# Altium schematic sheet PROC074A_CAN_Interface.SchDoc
size 431 x 279 mm; Date: Not shown in title block; ApprovedBy: Not shown in title block; CheckedBy: Not shown in title block; Author: Not shown in title block; CompanyName: Not shown in title block; Engineer: Not shown in title block; Organization: Not shown in title block; Address1: Not shown in title block; Address2: Not shown in title block; Address3: Not shown in title block; Address4: Not shown in title block; DocumentNumber: 1; Revision: Use project parameter SCH_Rev; SheetNumber: 13; SheetTotal: 22; PageSetup: Record=PageOptions¦CenterHorizontal=True¦CenterVertical=True¦PrintScale=1.00¦XCorrection=1.00¦YCorrection=1.00¦PrintKind=0¦BorderSize=5000000¦LeftOffset=0¦BottomOffset=0¦Orientation=2¦PaperLength=1000¦PaperWidth=1000¦Scale=100¦PaperSource=15¦PrintQuality=600¦MediaType=1¦DitherType=10¦PaperKind=Letter¦PrintScaleMode=1
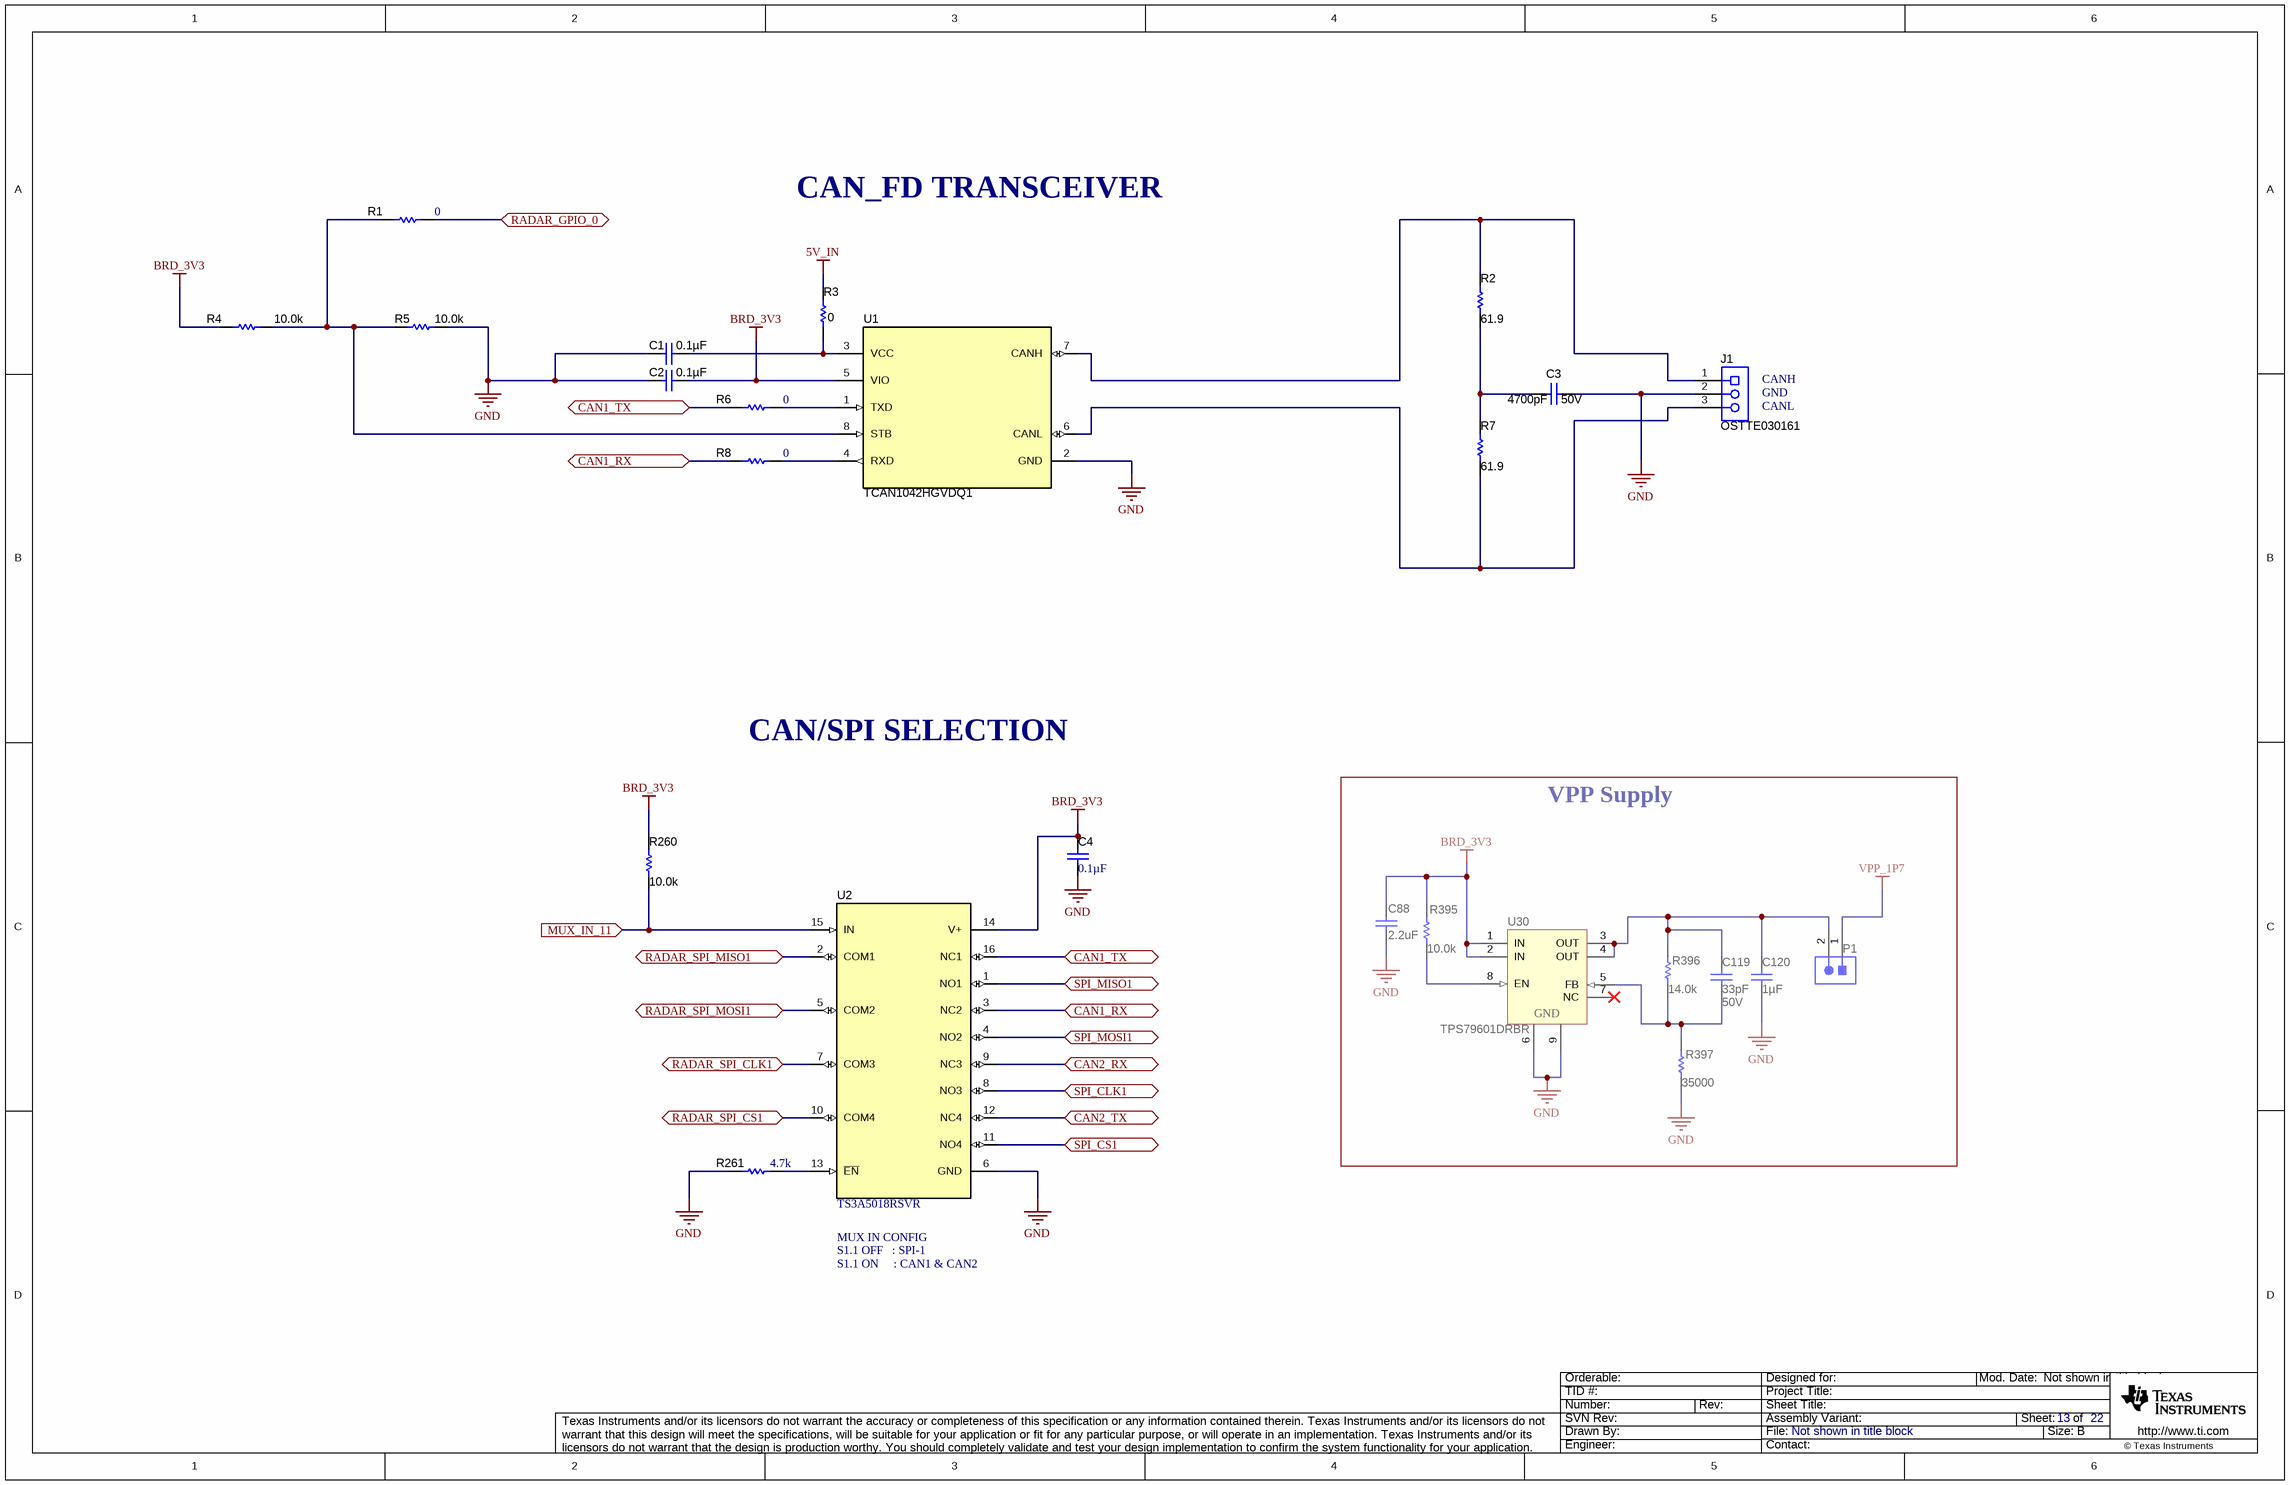
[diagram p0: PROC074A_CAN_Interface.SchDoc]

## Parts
C1  ValueDisplayed: 0.1µF  [0402L]  (hidden comment: C0402C104K8RACTU)
C2  ValueDisplayed: 0.1µF  [0402L]  (hidden comment: C0402C104K8RACTU)
C3  VDC_V: 50V  ValueDisplayed: 4700pF  [0402L]  (hidden comment: C1005X7R1H472K050BA)
C4  ValueDisplayed: 0.1µF  [0402]  (hidden comment: C0402C104K8RACTU)
C88  ValueDisplayed: 2.2uF  [0402_065L]  (hidden comment: C1005X7S1A225K050BC)
C119  VDC_V: 50V  ValueDisplayed: 33pF  [0402L]  (hidden comment: C0402C330J5GAC)
C120  ValueDisplayed: 1µF  [0402L]  (hidden comment: C1005X7S0J105M050BC)
J1  OSTTE030161  [On-Shore_OSTTE030161]
P1  TSW-102-07-G-S  [TSW-102-07-X-S]  (value not drawn)
R1  ValueDisplayed: 0  [0402]  (hidden comment: ERJ-2GE0R00X)
R2  ValueDisplayed: 61.9  [0402L]  (hidden comment: CRCW040261R9FKED)
R3  ValueDisplayed: 0  [0402L]  (hidden comment: ERJ-2GE0R00X)
R4  ValueDisplayed: 10.0k  [0402L]  (hidden comment: CRCW040210K0FKED)
R5  ValueDisplayed: 10.0k  [0402L]  (hidden comment: CRCW040210K0FKED)
R6  ValueDisplayed: 0  [0402]  (hidden comment: ERJ-2GE0R00X)
R7  ValueDisplayed: 61.9  [0402L]  (hidden comment: CRCW040261R9FKED)
R8  ValueDisplayed: 0  [0402]  (hidden comment: ERJ-2GE0R00X)
R260  ValueDisplayed: 10.0k  [0402L]  (hidden comment: CRCW040210K0FKED)
R261  ValueDisplayed: 4.7k  [0402]  (hidden comment: CRCW04024K70JNED)
R395  ValueDisplayed: 10.0k  [0402L]  (hidden comment: CRCW040210K0FKED)
R396  ValueDisplayed: 14.0k  [0402L]  (hidden comment: CRCW040214K0FKED)
R397  ValueDisplayed: 35000  [0402L]  (hidden comment: PNM0402E3502BST1)
U1  TCAN1042HGVDQ1  [D0008A_L]
U2  TS3A5018RSVR  [RSV0016A]
U30  TPS79601DRBR  [DRB0008B]

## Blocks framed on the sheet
VPP Supply: C88 C119 C120 P1 R395-R397 U30

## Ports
CAN1_RX, CAN1_TX, CAN2_RX, CAN2_TX, MUX_IN_11 (in), RADAR_GPIO_0, RADAR_SPI_CLK1, RADAR_SPI_CS1, RADAR_SPI_MISO1, RADAR_SPI_MOSI1, SPI_CLK1, SPI_CS1, SPI_MISO1, SPI_MOSI1

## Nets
5V_IN: R3.2
BRD_3V3: C2.2 C4.1 C88.2 R4.1 R260.2 R395.1 U1.5(VIO) U2.14(V+) U30.1(IN) U30.2(IN)
GND: C1.1 C2.1 C3.1 C4.2 C88.1 C120.1 J1.2 R5.2 R261.1 R397.1 U1.2(GND) U2.6(GND) U30.6(GND) U30.9(GND)
VPP_1P7: P1.1
CAN1_RX: R8.1 U2.3(NC2) ; port CAN1_RX
CAN1_TX: R6.1 U2.16(NC1) ; port CAN1_TX
CAN2_RX: U2.9(NC3) ; port CAN2_RX
CAN2_TX: U2.12(NC4) ; port CAN2_TX
MUX_IN_11: R260.1 U2.15(IN) ; port MUX_IN_11
RADAR_GPIO_0: R1.2 ; port RADAR_GPIO_0
RADAR_SPI_CLK1: U2.7(COM3) ; port RADAR_SPI_CLK1
RADAR_SPI_CS1: U2.10(COM4) ; port RADAR_SPI_CS1
RADAR_SPI_MISO1: U2.2(COM1) ; port RADAR_SPI_MISO1
RADAR_SPI_MOSI1: U2.5(COM2) ; port RADAR_SPI_MOSI1
SPI_CLK1: U2.8(NO3) ; port SPI_CLK1
SPI_CS1: U2.11(NO4) ; port SPI_CS1
SPI_MISO1: U2.1(NO1) ; port SPI_MISO1
SPI_MOSI1: U2.4(NO2) ; port SPI_MOSI1
NetC1_2: C1.2 R3.1 U1.3(VCC)
NetC3_2: C3.2 R2.1 R7.2
NetC119_1: C119.1 C120.2 P1.2 R396.2 U30.3(OUT) U30.4(OUT)
NetC119_2: C119.2 R396.1 R397.2 U30.5(FB)
NetJ1_1: J1.1 R2.2 U1.7(CANH)
NetJ1_3: J1.3 R7.1 U1.6(CANL)
NetR1_1: R1.1 R4.2 R5.1 U1.8(STB)
NetR6_2: R6.2 U1.1(TXD)
NetR8_2: R8.2 U1.4(RXD)
NetR261_2: R261.2 U2.13(~{EN})
NetR395_2: R395.2 U30.8(EN)

Not connected (* = marked no-connect by the designer): U30 7(NC)*

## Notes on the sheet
- CAN_FD TRANSCEIVER
- (near J1) CANH
- (near J1) GND
- (near J1) CANL
- CAN/SPI SELECTION
- MUX IN CONFIG
- S1.1 OFF   : SPI-1
- S1.1 ON     : CAN1 & CAN2

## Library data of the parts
C1 C2 = CMP-0078241-1: CAP, CERM, 0.1 µF, 10 V,+/- 10%, X7R, 0402; Manufacturer: Kemet; TaMin_C: -55°C; Polarized: N; SizeAreaWB_mm2: 3; U/M: EA; Value: 0.1uF; TaMax_C: 125°C; SizeZ_mm: 0.6; SizeX_mm: 1; SizeY_mm: 0.5; Cap_Case: 0402; Value2: 10V; CompType: Capacitor; Cap_F: 100nF; AEC Category: Q200
C3 = CMP-0078221-1: CAP, CERM, 4700 pF, 50 V,+/- 10%, X7R, 0402; Manufacturer: TDK; TaMin_C: -55°C; Polarized: N; SizeAreaWB_mm2: 3; U/M: EA; Value: 4700pF; TaMax_C: 125°C; SizeZ_mm: 0.6; SizeX_mm: 1; SizeY_mm: 0.5; Cap_Case: 0402; Cap_F: 4.7nF; AEC Category: Q200
C4 = CMP-0078241-1: CAP, CERM, 0.1 µF, 10 V,+/- 10%, X7R, 0402; Manufacturer: Kemet; TaMin_C: -55°C; Polarized: N; SizeAreaWB_mm2: 3; U/M: EA; Value: 0.1uF; TaMax_C: 125°C; SizeZ_mm: 0.6; SizeX_mm: 1; SizeY_mm: 0.5; Value2: 10V; CompType: Capacitor; Cap_F: 100nF; AEC Category: Q200
C88 = CMP-0006302-2: CAP, CERM, 2.2 uF, 10 V, +/- 10%, X7S, 0402; Manufacturer: TDK; TaMin_C: -55°C; ESR_ohm: 5.925m; Polarized: N; SizeAreaWB_mm2: 3; Value1: 0.005925 ohm; U/M: EA; Value: 2.2uF; TaMax_C: 125°C; SizeZ_mm: 0.65; SizeX_mm: 1; SizeY_mm: 0.5; Cap_Case: 0402_065; Value2: 10V; CompType: Capacitor; Cap_F: 2.2µF; IRMS_A: 2.05591A; AEC Category: Q200
C119 = CMP-0006242-2: CAP, CERM, 33 pF, 50 V, +/- 5%, C0G/NP0, 0402; Manufacturer: Kemet; TaMin_C: -55°C; Polarized: N; SizeAreaWB_mm2: 3; Value1: Unknown; U/M: EA; Value: 33pF; TaMax_C: 125°C; SizeZ_mm: 0.6; SizeX_mm: 1; SizeY_mm: 0.5; Cap_Case: 0402; AEC Category: Q200
C120 = CMP-0078222-1: CAP, CERM, 1 µF, 6.3 V,+/- 20%, X7S, 0402; Manufacturer: TDK; TaMin_C: -55°C; Polarized: N; SizeAreaWB_mm2: 3; U/M: EA; Value: 1uF; TaMax_C: 125°C; SizeZ_mm: 0.6; SizeX_mm: 1; SizeY_mm: 0.5; Cap_Case: 0402; Value2: 6.3V; CompType: Capacitor; AEC Category: Q200
J1 = CMP-0075352-1: Terminal Block, 3.5mm, 3x1, Tin, R/A, TH; Manufacturer: On-Shore Technology; CNHeader: False; Current_A: 10A; Green_Lifecycle: Not Set; Gender: Female; Cert_CSA: Y; Green_REACh: Incomplete; Voltage_V: 125V; Row_Count: 1; Pitch_mm: 3.5; CT: True
P1 = CMP-0075405-1: Header, 100mil, 2x1, Gold, TH; Manufacturer: Samtec; Pitch_mm: 2.54; Cert_VDE: N; Gender: Male; Cert_CSA: Y; Voltage_V: 550V; Green_REACh: Passed; Current_A: 6.3A; CT: False; Green_Lifecycle: Active; Row_Count: 1; CNHeader: True
R1 R6 R8 = CMP-0026992-3: RES, 0, 5%, 0.1 W, AEC-Q200 Grade 0, 0402; Manufacturer: Panasonic; Power_W: 100mW; TempCo: 600 ppm/C; Value_Code: 0000; Value: 0; EIA_Code: E24; SizeX_mm: 1; SizeY_mm: 0.5; SizeZ_mm: 0.6; Value2: 0.1W; CompType: Resistor; AEC Qualified: Y; VDC_V: 50V; AEC Category: Q200; SizeAreaWB_mm2: 3; INSTALLATION: DNP
R2 R7 = CMP-0026491-1: RES, 61.9, 1%, 0.063 W, 0402; Manufacturer: Vishay-Dale; Power_W: 63mW; TempCo: 100 ppm/C; Value_Code: 61R9; U/M: EA; Value: 61.9; EIA_Code: E96; SizeX_mm: 1; SizeY_mm: 0.5; SizeZ_mm: 0.6; Value2: 0.063W; VDC_V: 50V; AEC Category: Q200
R3 = CMP-0026992-2: RES, 0, 5%, 0.063 W, 0402; Manufacturer: Panasonic; Power_W: 63mW; TempCo: 600 ppm/C; Value_Code: 0000; U/M: EA; Value: 0; EIA_Code: E24; SizeX_mm: 1; SizeY_mm: 0.5; SizeZ_mm: 0.6; Value2: 0.063W; VDC_V: 50V; AEC Category: Q200
R4 = CMP-0025958-2: RES, 10.0 k, 1%, 0.063 W, 0402; Manufacturer: Vishay-Dale; Power_W: 63mW; TempCo: 100 ppm/C; Value_Code: 10k0; U/M: EA; Value: 10.0k; EIA_Code: E96; Res_ohm: 10k; SizeX_mm: 1; SizeY_mm: 0.5; SizeZ_mm: 0.6; Value2: 0.063W; CompType: Resistor; VDC_V: 50V; AEC Category: Q200; INSTALLATION: DNP
R5 R260 R395 = CMP-0025958-2: RES, 10.0 k, 1%, 0.063 W, 0402; Manufacturer: Vishay-Dale; Power_W: 63mW; TempCo: 100 ppm/C; Value_Code: 10k0; U/M: EA; Value: 10.0k; EIA_Code: E96; Res_ohm: 10k; SizeX_mm: 1; SizeY_mm: 0.5; SizeZ_mm: 0.6; Value2: 0.063W; VDC_V: 50V; AEC Category: Q200
R261 = CMP-0026938-5: RES, 4.7 k, 5%, 0.063 W, AEC-Q200 Grade 0, 0402; Manufacturer: Vishay-Dale; Power_W: 63mW; TempCo: 200 ppm/C; Value_Code: 4k70; Value: 4.7k; EIA_Code: E24; SizeX_mm: 1; SizeY_mm: 0.5; SizeZ_mm: 0.6; Value2: 0.063W; AEC Qualified: Y; VDC_V: 50V; AEC Category: Q200; AEC Grade: 0
R396 = CMP-0026015-2: RES, 14.0 k, 1%, 0.063 W, 0402; Manufacturer: Vishay-Dale; Power_W: 63mW; TempCo: 100 ppm/C; Value_Code: 14k0; U/M: EA; Value: 14.0k; EIA_Code: E96; Res_ohm: 14k; SizeX_mm: 1; SizeY_mm: 0.5; SizeZ_mm: 0.6; Value2: 0.063W; VDC_V: 50V; AEC Category: Q200
R397 = CMP-0078213-1: RES, 35000, 0.1%, 0.05 W, 0402; Manufacturer: Vishay-Dale; Value_Code: 35k0; SizeArea_mm2: 0.5; AEC Qualified: N; AEC Category: Q200; Res_ohm: 35k; Value: 35.0k; SizeZ_mm: 0.6; TempCo: 25 ppm/C; Power_W: 50mW; VDC_V: 75V; Value2: 0.05W; U/M: EA; SizeX_mm: 1
U1 = CMP-0075992-1: Automotive Fault Protected CAN Transceiver With Flexible Data-Rate, D0008A (SOIC-8); Manufacturer: Texas Instruments; Alternate PartNumber: TCAN1042HGVDRQ1; SizeAreaWB_mm2: 56.58; SizeArea_mm2: 30.38; SizeZ_mm: 1.75; SizeY_mm: 6.2; U/M: EA; CompType: IC; SizeX_mm: 4.9
U2 = CMP-0067415-1: 10-Ohm Quad SPDT Analog Switch, RSV0016A (UQFN-16); Alternate Manufacturer: Texas Instruments; SizeAreaWB_mm2: 10.08; U/M: EA; SizeZ_mm: 0.55; SizeX_mm: 1.8; SizeY_mm: 2.6; SizeArea_mm2: 4.68; CompType: IC
U30 = CMP-0036402-2: Single Output High PSRR LDO, 1 A, Adjustable 1.2 to 5.5 V Output, 2.7 to 5.5 V Input, 8-pin SON (DRB), -40 to 125 degC, Green (RoHS & no Sb/Br); Manufacturer: Texas Instruments; Vin(Min)(V): 2.7; Vout Adj(Max)(V): 5.5; Vout Adj(Min)(V): 1.2; Accuracy(%): 2; SubFamily: Single Channel LDO; Iq(Typ)(mA): 0.26; Vdo(Typ)(mV): 250; Iout(Max)(A): 1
